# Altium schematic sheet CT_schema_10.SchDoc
size 278 x 170 mm
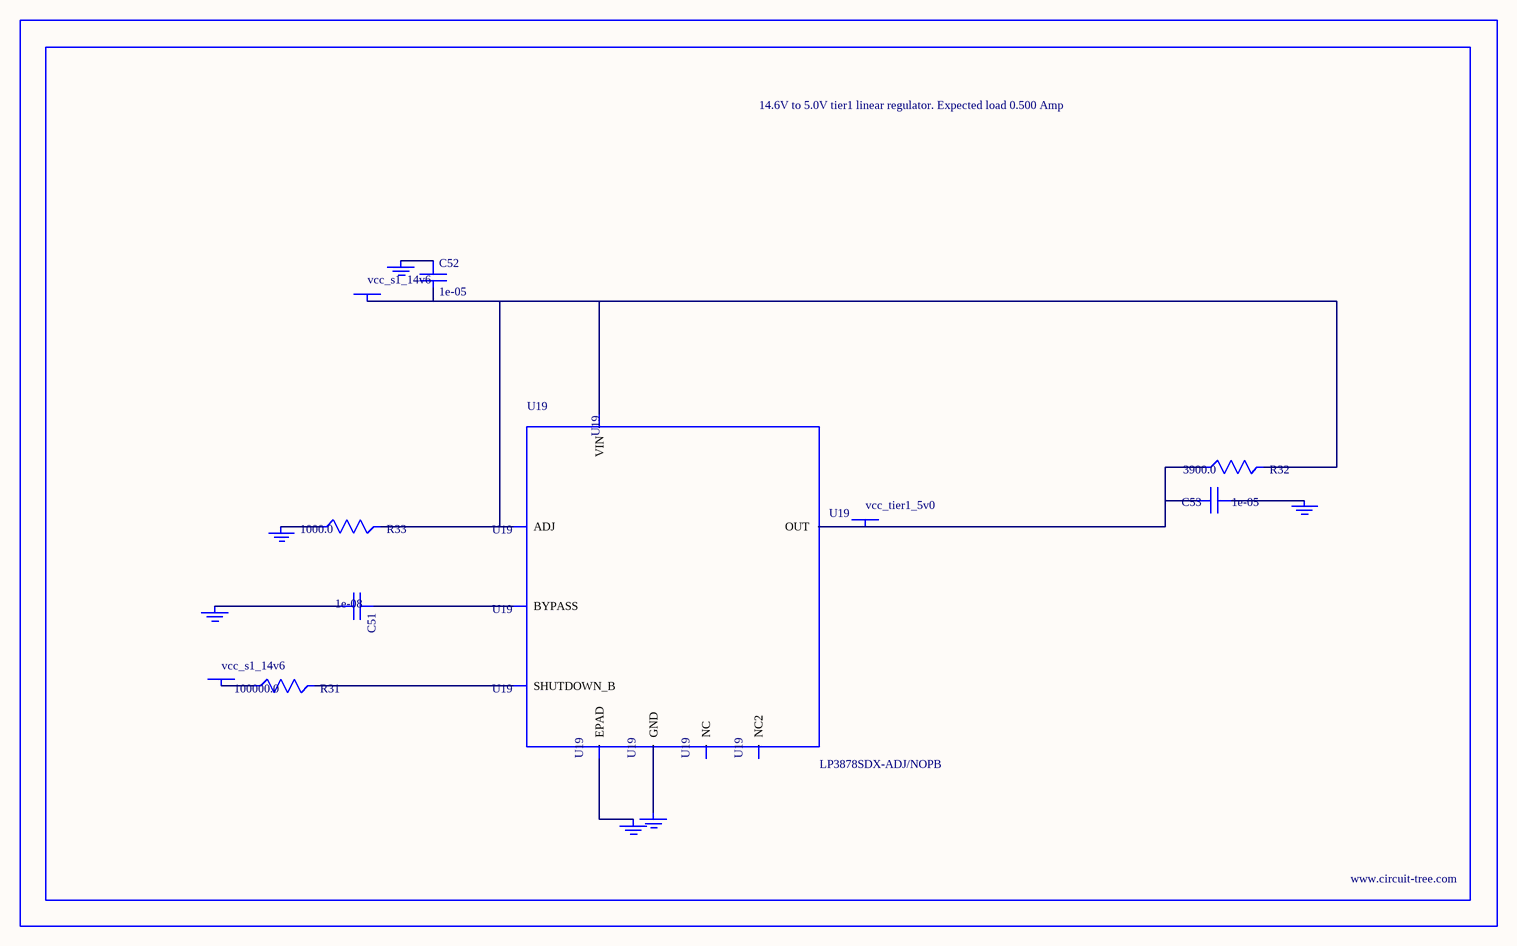
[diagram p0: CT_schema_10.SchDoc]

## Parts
BORDER9  (no value)
C51  1e-08  [C0402]
C52  1e-05  [C1210]
C53  1e-05  [C1210]
GND_INSTANCE_9_0  (no value)
GND_INSTANCE_9_1  (no value)
GND_INSTANCE_9_2  (no value)
GND_INSTANCE_9_3  (no value)
GND_INSTANCE_9_4  (no value)
GND_INSTANCE_9_5  (no value)
POWER_INSTANCE_9_0  vcc_s1_14v6
POWER_INSTANCE_9_1  vcc_s1_14v6
POWER_INSTANCE_9_2  vcc_tier1_5v0
R31  100000.0  [R0603]
R32  3900.0  [R0603]
R33  1000.0  [R0603]
U19  LP3878SDX-ADJ/NOPB  [WSON-8]

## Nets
NetC51_1: C51.1 U19.1(BYPASS)
NetC51_2: C51.2 GND_INSTANCE_9_0.0(GND)
NetC52_1: C52.1 GND_INSTANCE_9_1.0(GND)
NetC52_2: C52.2 POWER_INSTANCE_9_0.0(PWR) R32.2 R33.2 U19.4(VIN) U19.6(ADJ)
NetC53_1: C53.1 GND_INSTANCE_9_2.0(GND)
NetC53_2: C53.2 POWER_INSTANCE_9_2.0(PWR) R32.1 U19.5(OUT)
NetGND_INSTANCE_9_3_0: GND_INSTANCE_9_3.0(GND) R33.1
NetGND_INSTANCE_9_4_0: GND_INSTANCE_9_4.0(GND) U19.PAD(EPAD)
NetGND_INSTANCE_9_5_0: GND_INSTANCE_9_5.0(GND) U19.3(GND)
NetPOWER_INSTANCE_9_1_0: POWER_INSTANCE_9_1.0(PWR) R31.1
NetR31_2: R31.2 U19.8(SHUTDOWN_B)

Not connected (* = marked no-connect by the designer): U19 2(NC) 7(NC2)

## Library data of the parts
BORDER9 = BORDER_PAGE9
C51 = C0402C103K3RAC
C52 = C1210C106K5PACTU
C53 = GRM32DR61E106MA12L
GND_INSTANCE_9_0-GND_INSTANCE_9_5 = GND
POWER_INSTANCE_9_0-POWER_INSTANCE_9_2 = PWR
R31 = RC0603JR-07100KL
R32 = RC0603JR-073K9L
R33 = RC0603JR-071KL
